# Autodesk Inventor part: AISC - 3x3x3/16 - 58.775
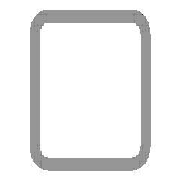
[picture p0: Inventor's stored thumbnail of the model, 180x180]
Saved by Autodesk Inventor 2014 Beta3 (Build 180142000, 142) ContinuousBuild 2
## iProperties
IsCustomPart: 1
_CCFamilyMember: 9
_CCFamilyDisplayName: ANSI AISC (Square) - Tube
_FrameMemberDoc: Frame Member File
_Version: 15.0.0
_GetPNFromCC: 1
Created: 2011-01
Part Number: AISC - 3x3x3/16 - 58.775
Material: Steel, Mild
Description: Tube
Document SubType Name: Modeling
Standard: ANSI
Designer: Beta-8540w
Standards Organization: ANSI
Language: en-US
Size Designation: 3x3x3/16
Categories: <MemberInstance><Categories><Category DisplayName="Structural Shapes" InternalName="089c4875-fa83-4c05-b084-43b9cc11f5ed" Mnemonic="GRDR"><CategoryParameter Dis
Stock Number: 3x3x3/16
Density: 7.86 g/cm^3
Appearance: Steel
G_L: 58.775 in
G_W: 3.000 in
G_H: 3.000 in
+F1DD31D7-8EA7-4030-B73F-B4109CE49B1F+CUTDETAIL1: Cut
Author: Beta-8540w
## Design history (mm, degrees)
node "Start plane"
node "End plane"
sketch "Sketch"
  geometry: L1 (-38.1, -28.575)-(-38.1, 28.575); L2 (-28.575, 38.1)-(28.575, 38.1); L3 (38.1, 28.575)-(38.1, -28.575); L4 (28.575, -38.1)-(-28.575, -38.1); L5 (-28.575, 33.337)-(28.575, 33.338); L6 (33.338, 28.575)-(33.338, -28.575); L7 (28.575, -33.337)-(-28.575, -33.338); L8 (-33.338, -28.575)-(-33.338, 28.575); L9 (0, 56.102)-(0, -56.102) reference; L10 (-56.102, 0)-(56.102, 0) reference; A1 r 9.525 centre (-28.575, -28.575) between (-38.1, -28.575) and (-28.575, -38.1); A2 r 9.525 centre (-28.575, 28.575) between (-28.575, 38.1) and (-38.1, 28.575); A3 r 9.525 centre (28.575, 28.575) between (38.1, 28.575) and (28.575, 38.1); A4 r 9.525 centre (28.575, -28.575) between (28.575, -38.1) and (38.1, -28.575); A5 r 4.763 centre (-28.575, 28.575) between (-28.575, 33.337) and (-33.338, 28.575); A6 r 4.763 centre (28.575, 28.575) between (33.338, 28.575) and (28.575, 33.338); A7 r 4.763 centre (28.575, -28.575) between (28.575, -33.337) and (33.338, -28.575); A8 r 4.763 centre (-28.575, -28.575) between (-33.338, -28.575) and (-28.575, -33.338)
  constraints: 16 end point, 16 point on circle, 8 centre point, 8 tangent, 4 parallel, 3 equal radius, 2 perpendicular, 7 other
  dimensions: "d10" = 76.2 distance between parallel lines of L2 L4 (= G_H); "d11" = 76.2 distance between parallel lines of L1 L3 (= G_W); "d12" = 4.7625 distance between parallel lines of L3 L6 (= G_T); "d15" = 38.1 distance between parallel lines of L2 L10 (= 0.5 x d10); "d16" = 38.1 distance between parallel lines of L9 L3 (= 0.5 x d11); "d17" = 9.525 radius of A1 (= G_IR)
extrude "Body" new body sketch "Sketch" stored distance "d3" = 1492.89148 (= G_L); taper "d4" = 0 deg
node "Driven Length"
  sketch "Sketch3"
    geometry: L1 (0, 0)-(10, 0) reference
    constraints: 2 end point, 1 horizontal
  workplane "Work Plane3"
  sketch "Sketch4"
    geometry: L1 (-2, 31.109)-(12, 31.109) reference; L2 (-2, 1524)-(12, 1524) reference
    dimensions: "d19" = 1492.89148 distance between parallel lines of L1 L2 (derived)
workplane "Work Plane4"
split "Split1"
body "Solid1"
other parameters: "G_W" = 76.2 [user parameter; used in 1 equation term], "G_H" = 76.2 [user parameter; used in 1 equation term], "G_T" = 4.7625 [user parameter; used in 1 equation term], "G_IR" = 9.525 [user parameter; used in 1 equation term], "G_L" = 1492.89148 (= d19) [user parameter; used in 1 equation term], "G_OFFSET_START" = -31.10852 [user parameter; used in 1 equation term], "G_OFFSET_END" = 0 [user parameter; used in 1 equation term], "d13" = 31.10852 (= -G_OFFSET_START), "d14" = 1524 (= G_OFFSET_END + B_L), "B_L" = 1524 [user parameter; used in 1 equation term], "d18" = 90 deg
